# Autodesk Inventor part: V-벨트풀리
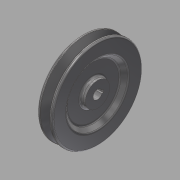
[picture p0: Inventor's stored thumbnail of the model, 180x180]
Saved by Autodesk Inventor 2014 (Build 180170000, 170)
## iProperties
Created: 2015-12
Part Number: V-벨트풀리
Document SubType Name: Modeling
Designer: mdu
Density: 7.87 g/cm^3
Material: 강철, 탄소
Appearance: 반연마
Mass: 1106 g
Surface Area: 369.462 cm^2
Volume: 140.533 cm^3
Author: mdu
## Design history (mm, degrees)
sketch "스케치1"
  geometry: L1 (-10, 0)-(10, 0); L2 (-10, 0)-(-10, 16); L3 (-10, 16)-(-4, 16); L4 (-4, 16)-(-4, 35); L5 (-4, 35)-(-10, 41); L6 (-10, 41)-(-10, 59.5); L7 (-10, 59.5)-(-6.062, 59.5); L8 (-6.062, 59.5)-(-2.001, 47); L9 (-2.001, 47)-(2.001, 47); L10 (2.001, 47)-(6.062, 59.5); L11 (6.062, 59.5)-(10, 59.5); L12 (10, 59.5)-(10, 41); L13 (10, 41)-(4, 35); L14 (4, 35)-(4, 16); L15 (4, 16)-(10, 16); L16 (10, 16)-(10, 0); L17 (-4.6, 55)-(4.6, 55); 2 further points
  constraints: 34 end point, 7 parallel, 6 equal length, 5 collinear, 3 perpendicular, 2 point on line, 1 coincident, 1 horizontal, 1 midpoint
  dimensions: "d0" = 20 distance of L1.start L1.end; "d1" = 9.2 distance of L17.start L17.end; "d2" = 36 deg angle of L10 L8; "d3" = 4.5 distance between parallel lines of L7 L17; "d4" = 8 distance between parallel lines of L9 L17; "d6" = 110 diameter of L17 L1; "d7" = 32 diameter of L3 L1; "d8" = 82 diameter of L5.end L1; "d9" = 6 distance of L2.end L3.end; "d10" = 135 deg angle of L4 L5
revolve "회전1" sketch "스케치1" stored, may be unused: angle "d11" = 90 deg
fillet "모깎기1" dims "d12" = 2, "d13" = 0.5, "d14" = 1, "d15" = 3
sketch "스케치2"
  geometry: L1 (-2, 5.657)-(-2, 7.8); L2 (-2, 7.8)-(2, 7.8); L3 (2, 7.8)-(2, 5.657); A1 r 6 centre (0, 0) between (-2, 5.657) and (2, 5.657); 1 further point
  constraints: 6 end point, 2 parallel, 2 point on circle, 1 centre point, 1 coincident, 1 perpendicular, 1 vertical
  dimensions: "d16" = 12 diameter of A1; "d17" = 4 distance of L1.end L2.end; "d18" = 13.8 dimension on A1 L2 (computed from d16)
extrude "돌출1" cut sketch "스케치2" stored distance "d19" = 10; taper "d20" = 0 deg
node "솔리드1"
